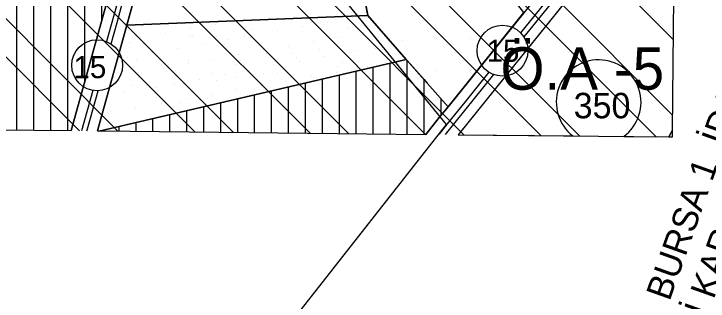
# Model space of a CAD drawing. Extents: x 409341 to 428634, y 4447481 to 4463281.
# Drawn here: x 420906.8 to 421316.4, y 4457678.8 to 4457848 of the extents above; entities that cross this region are included whole.
import ezdxf

# ---------------------------------------------------------------- set-up
doc = ezdxf.new("R2010")
doc.units = 0
for name, color, linetype in [('ADA', 7, 'Continuous'), ('ADAKENARI', 7, 'Continuous'), ('Default', 7, 'Continuous'), ('KALDIRIM', 7, 'Continuous'), ('KD_DAIRE', 7, 'Continuous'), ('KD_YGEN', 7, 'Continuous'), ('OA5', 7, 'Continuous'), ('PL_AYA_PARK_DINLENME', 7, 'Continuous'), ('PL_EĞİTİM', 7, 'Continuous'), ('PL_KON_MEV_250', 7, 'Continuous'), ('PL_KON_ONE_350', 7, 'Continuous'), ('SM_DAIRE', 7, 'Continuous'), ('SM_TAKS', 7, 'Continuous'), ('SN_TR_SIVILASMA', 7, 'Continuous'), ('TR_EĞİTİM', 7, 'Continuous'), ('TR_ORTAGELISME', 7, 'Continuous'), ('TR_ORTAYOGUNKONUT', 7, 'Continuous'), ('TR_PARKALANI', 7, 'Continuous')]:
    doc.layers.add(name, color=color, linetype=linetype)

# ---------------------------------------------------------------- blocks, each defined once
blk = doc.blocks.new('POINT_DISPLAY')
at = {"layer": 'Default'}
blk.add_line((0, 0), (0, 0), dxfattribs=at)

msp = doc.modelspace()

# ---------------------------------------------------------------- linework, layer by layer
at = {"layer": 'ADA'}
for p, q in [((421104.42, 4457904.65), (421115.69, 4457847.13)), ((421115.69, 4457847.13), (420973.4, 4457841.41)), ((421115.69, 4457847.13), (421138.25, 4457821.19)), ((421115.69, 4457847.13), (421138.25, 4457821.19)), ((421115.69, 4457847.13), (421138.25, 4457821.19)), ((420957.84, 4457779.09), (421138.25, 4457821.19)), ((421138.25, 4457821.19), (421162.95, 4457793.32)), ((421138.25, 4457821.19), (421162.95, 4457793.32)), ((421138.25, 4457821.19), (421150.6, 4457807.25)), ((421150.6, 4457807.25), (421162.95, 4457793.32)), ((421293.17, 4457775.55), (421295.4, 4457779.52))]:
    msp.add_line(p, q, dxfattribs=at)
at = {"layer": 'ADAKENARI'}
for p, q in [((420986.52, 4457944.4), (420940.52, 4457779.27)), ((420973.4, 4457841.41), (421000.97, 4457940.37)), ((421262.59, 4457892.95), (421168.94, 4457776.86)), ((421231.61, 4457878.44), (421162.95, 4457793.32)), ((421231.61, 4457878.44), (421162.95, 4457793.32)), ((421231.61, 4457878.44), (421162.95, 4457793.32)), ((420956.05, 4457779.11), (420973.4, 4457841.41)), ((421162.95, 4457793.32), (421157.8, 4457786.95)), ((421157.8, 4457786.95), (421149.83, 4457777.06))]:
    msp.add_line(p, q, dxfattribs=at)
at = {"layer": 'Default'}
msp.add_lwpolyline([(421050.15, 4457417.04), (421007.83, 4457463.42), (420944.65, 4457570.66), (421072.18, 4457668.63), (421162.04, 4457782.83), (421104.64, 4457852.98), (421094.21, 4457913.27), (421166.67, 4457928.34), (421162.04, 4458023.99), (421167.25, 4458044.28), (421186.38, 4458040.8), (421198.56, 4458072.69), (421246.09, 4458061.67), (421231.6, 4458019.35), (421275.66, 4457988.05), (421219.43, 4457901.09), (421239.14, 4457880.8), (421273.92, 4457924.86), (421286.67, 4457976.46), (421297.69, 4458041.38), (421309.86, 4458162.54), (421241.45, 4458159.64), (421240.3, 4458303.41)], dxfattribs=at)
at = {"layer": 'KALDIRIM'}
for p, q in [((420992.3, 4457942.79), (420961.36, 4457831.73)), ((420967.62, 4457843.02), (420995.19, 4457941.98)), ((421273.79, 4457916.39), (421207.69, 4457834.45)), ((421236.28, 4457874.67), (421205.77, 4457836.85)), ((420964.09, 4457830.32), (420967.62, 4457843.02)), ((421187.06, 4457813.66), (421172.78, 4457795.95)), ((421189.81, 4457812.29), (421161.29, 4457776.94)), ((420953.36, 4457802.98), (420946.74, 4457779.21)), ((420950.14, 4457780.25), (420956.42, 4457802.78)), ((421172.78, 4457795.95), (421162.47, 4457783.18)), ((420949.84, 4457779.18), (420950.14, 4457780.25)), ((421162.47, 4457783.18), (421157.47, 4457776.98))]:
    msp.add_line(p, q, dxfattribs=at)
at = {"layer": 'KD_DAIRE'}
for centre in [(421195.08, 4457826.33), (420955.86, 4457817.77)]:
    msp.add_circle(centre, 15, dxfattribs=at)
at = {"layer": 'PL_AYA_PARK_DINLENME'}
for p, q in [((420956.05, 4457779.11), (420957.84, 4457779.09)), ((421295.4, 4457779.52), (421293.17, 4457775.55))]:
    msp.add_line(p, q, dxfattribs=at)
for points in [[(420957.84, 4457779.09), (421138.25, 4457821.19), (421115.69, 4457847.13), (420973.4, 4457841.41), (420956.05, 4457779.11)], [(421293.17, 4457775.55), (421295.36, 4457775.52), (421295.4, 4457779.52)]]:
    msp.add_lwpolyline(points, dxfattribs=at)
at = {"layer": 'PL_EĞİTİM'}
msp.add_lwpolyline([(421207.76, 4457848.88), (421161.3, 4457908.23), (421148.7, 4457917.92), (421125.85, 4457911.41), (421104.42, 4457904.65), (421115.69, 4457847.13), (421138.25, 4457821.19), (421138.82, 4457820.55), (421148.82, 4457809.27), (421150.6, 4457807.25), (421162.95, 4457793.32), (421207.76, 4457848.88)], dxfattribs=at)
at = {"layer": 'PL_KON_MEV_250'}
for p, q in [((420940.52, 4457779.27), (420986.52, 4457944.4)), ((420822.23, 4457780.52), (420940.52, 4457779.27)), ((420957.84, 4457779.09), (421149.83, 4457777.06))]:
    msp.add_line(p, q, dxfattribs=at)
for points in [[(421000.97, 4457940.37), (420973.4, 4457841.41), (421115.69, 4457847.13), (421104.42, 4457904.65), (421125.85, 4457911.41), (421110.62, 4457996.56), (421168.14, 4458007.84), (421173.36, 4458034.24), (421194.4, 4458031.48), (421195.6, 4458036.07), (421202.94, 4458066.69), (421237.29, 4458058.84), (421222.97, 4458017.27), (421265.39, 4457988.9), (421209.89, 4457896.73), (421214.41, 4457892.92), (421231.61, 4457878.44), (421266.78, 4457922.04)], [(421149.83, 4457777.06), (421157.8, 4457786.95), (421162.95, 4457793.32), (421138.25, 4457821.19), (420957.84, 4457779.09)]]:
    msp.add_lwpolyline(points, dxfattribs=at)
at = {"layer": 'PL_KON_ONE_350'}
for p, q in [((421295.4, 4457779.52), (421296.46, 4457880.64)), ((421168.94, 4457776.86), (421293.17, 4457775.55)), ((421293.17, 4457775.55), (421295.4, 4457779.52))]:
    msp.add_line(p, q, dxfattribs=at)
msp.add_lwpolyline([(421296.46, 4457880.64), (421268.58, 4457894.28), (421262.59, 4457892.95), (421168.94, 4457776.86)], dxfattribs=at)
at = {"layer": 'SM_DAIRE'}
msp.add_line((421236.58, 4457776.14), (421266.66, 4457775.83), dxfattribs=at)
msp.add_arc((421251.83, 4457795.95), 25, 306.3763, 232.4122, dxfattribs=at)
at = {"layer": 'SN_TR_SIVILASMA'}
for p, q in [((421295.96, 4457832.82), (420847.49, 4458281.29)), ((421295.5, 4457788.39), (420847.49, 4458236.39)), ((421285.81, 4457775.62), (420847.49, 4458213.94)), ((421240.43, 4457776.1), (420847.49, 4458169.04)), ((421217.74, 4457776.34), (420847.49, 4458146.59)), ((420945.45, 4457779.22), (420581.04, 4458143.63)), ((420968.14, 4457778.98), (420603.49, 4458143.63)), ((421013.52, 4457778.5), (420648.4, 4458143.63)), ((421036.21, 4457778.26), (420670.85, 4458143.63)), ((421149.66, 4457777.06), (420783.1, 4458143.63)), ((421172.36, 4457776.82), (420805.55, 4458143.63)), ((421104.28, 4457777.54), (420872.43, 4458009.39)), ((421081.59, 4457777.78), (420863.44, 4457995.94))]:
    msp.add_line(p, q, dxfattribs=at)
at = {"layer": 'TR_ORTAGELISME'}
for p, q in [((421295.4, 4457779.52), (421296.46, 4457880.64)), ((421168.94, 4457776.86), (421236.58, 4457776.14)), ((421266.66, 4457775.83), (421293.17, 4457775.55)), ((421293.17, 4457775.55), (421295.4, 4457779.52))]:
    msp.add_line(p, q, dxfattribs=at)
msp.add_lwpolyline([(421296.46, 4457880.64), (421268.58, 4457894.28), (421262.59, 4457892.95), (421168.94, 4457776.86)], dxfattribs=at)
msp.add_arc((421251.83, 4457795.95), 25, 306.3763, 232.4122, dxfattribs=at)
at = {"layer": 'TR_ORTAYOGUNKONUT'}
for p, q in [((420908.59, 4457779.61), (420908.59, 4458334.88)), ((420918.59, 4457779.51), (420918.59, 4458334.8)), ((420928.59, 4457779.4), (420928.59, 4458333.66)), ((420938.59, 4457779.29), (420938.59, 4458331.65)), ((420948.59, 4457808.23), (420948.59, 4458065.76)), ((420958.59, 4457844.13), (420958.59, 4458040.79)), ((421138.82, 4457777.18), (421138.82, 4457820.55)), ((421118.82, 4457777.39), (421118.82, 4457816.65)), ((421128.82, 4457777.28), (421128.82, 4457818.98)), ((421108.82, 4457777.49), (421108.82, 4457814.32)), ((421088.82, 4457777.71), (421088.82, 4457809.65)), ((421098.82, 4457777.6), (421098.82, 4457811.98)), ((421148.82, 4457777.07), (421148.82, 4457809.27)), ((421068.82, 4457777.92), (421068.82, 4457804.98)), ((421078.82, 4457777.81), (421078.82, 4457807.32)), ((421048.82, 4457778.13), (421048.82, 4457800.32)), ((421058.82, 4457778.02), (421058.82, 4457802.65)), ((421038.82, 4457778.23), (421038.82, 4457797.98)), ((421158.82, 4457788.2), (421158.82, 4457797.98)), ((421018.82, 4457778.45), (421018.82, 4457793.32)), ((421028.82, 4457778.34), (421028.82, 4457795.65)), ((420998.82, 4457778.66), (420998.82, 4457788.65)), ((421008.82, 4457778.55), (421008.82, 4457790.98)), ((420978.82, 4457778.87), (420978.82, 4457783.98)), ((420988.82, 4457778.76), (420988.82, 4457786.32)), ((420968.82, 4457778.97), (420968.82, 4457781.65)), ((420958.82, 4457779.08), (420958.82, 4457779.32))]:
    msp.add_line(p, q, dxfattribs=at)
for points in [[(421000.97, 4457940.37), (420973.4, 4457841.41), (421115.69, 4457847.13), (421104.42, 4457904.65), (421125.85, 4457911.41), (421110.62, 4457996.56), (421168.14, 4458007.84), (421173.36, 4458034.24), (421194.4, 4458031.48), (421195.6, 4458036.07), (421202.94, 4458066.69), (421237.29, 4458058.84), (421222.97, 4458017.27), (421265.39, 4457988.9), (421209.89, 4457896.73), (421214.41, 4457892.92), (421231.61, 4457878.44), (421266.78, 4457922.04)], [(420940.52, 4457779.27), (420986.52, 4457944.4)]]:
    msp.add_lwpolyline(points, dxfattribs=at)

# ---------------------------------------------------------------- block references
at = {"layer": 'TR_EĞİTİM', "xscale": 0.1, "yscale": 0.10000000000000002}
for p in [(421156.18, 4457833.43), (421176.39, 4457833.74), (421194.74, 4457833.43), (421136.3, 4457832.45), (421156.18, 4457814.72), (421175.94, 4457814.94)]:
    msp.add_blockref('POINT_DISPLAY', p, dxfattribs=at)
at = {"layer": 'TR_PARKALANI', "xscale": 0.1, "yscale": 0.10000000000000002}
for p in [(421106.54, 4457845.82), (421106.54, 4457845.82), (421026.02, 4457841.77), (421026.02, 4457841.77), (421082.52, 4457842.92), (421082.52, 4457842.92), (421089.52, 4457841.89), (421091.77, 4457843.21), (421091.77, 4457843.21), (421119.93, 4457841.61), (421119.93, 4457841.61), (420982.64, 4457840.43), (420986.5, 4457840.67), (421011.25, 4457839.17), (421011.25, 4457839.17), (421046.69, 4457838.96), (421046.69, 4457838.96), (421062.23, 4457838), (421062.23, 4457838), (421077, 4457840.61), (421077, 4457840.61), (421104.29, 4457839.29), (420981.71, 4457833.96), (420981.71, 4457833.96), (420996.48, 4457836.57), (420996.48, 4457836.57), (421010.85, 4457835), (421010.85, 4457835), (421012.18, 4457835.22), (421042.59, 4457834.93), (421047.45, 4457835.4), (421047.45, 4457835.4), (421098.43, 4457834.23), (421098.43, 4457834.23), (421113.2, 4457836.84), (421113.2, 4457836.84), (420975.01, 4457831.03), (420975.01, 4457831.03), (421017.91, 4457830.19), (421017.91, 4457830.19), (421026.95, 4457832.62), (421032.68, 4457832.79), (421032.68, 4457832.79), (421068.89, 4457829.02), (421068.89, 4457829.02), (421083.66, 4457831.63), (421083.66, 4457831.63), (420988.37, 4457824.98), (420988.37, 4457824.98), (421003.14, 4457827.59), (421003.14, 4457827.59), (421054.12, 4457826.42), (421054.12, 4457826.42), (421056.5, 4457827.41), (421071.27, 4457824.8), (421086.91, 4457827.12), (421105.09, 4457825.25), (421105.09, 4457825.25), (421109.47, 4457826.37), (421119.86, 4457827.86), (421119.86, 4457827.86), (420973.59, 4457822.38), (420973.59, 4457822.38), (420979.17, 4457820.73), (421024.57, 4457821.21), (421024.57, 4457821.21), (421039.34, 4457823.81), (421039.34, 4457823.81), (421073.63, 4457822.4), (421090.32, 4457822.65), (421090.32, 4457822.65), (421133.81, 4457820.69), (421133.81, 4457820.69), (420993.94, 4457818.13), (421009.58, 4457820.45), (421009.8, 4457818.61), (421009.8, 4457818.61), (421037.79, 4457818.44), (421060.78, 4457817.44), (421060.78, 4457817.44), (421075.55, 4457820.04), (421075.55, 4457820.04), (421097.98, 4457816.73), (421097.98, 4457816.73), (421100.81, 4457819.59), (421115.59, 4457816.99), (421126.52, 4457818.88), (421126.52, 4457818.88), (420980.25, 4457813.4), (420980.25, 4457813.4), (420995.03, 4457816), (420995.03, 4457816), (421001.96, 4457814.48), (421023.48, 4457812.92), (421046, 4457814.83), (421046, 4457814.83), (421053.89, 4457812.63), (421062.14, 4457812.76), (421062.14, 4457812.76), (421096.98, 4457813.67), (421096.98, 4457813.67), (421111.75, 4457816.27), (421111.75, 4457816.27), (420965.48, 4457810.79), (420965.48, 4457810.79), (420966.12, 4457810.52), (421016.46, 4457809.63), (421016.46, 4457809.63), (421026.3, 4457808.8), (421026.3, 4457808.8), (421031.23, 4457812.23), (421031.23, 4457812.23), (421038.25, 4457810.31), (421067.44, 4457808.46), (421067.44, 4457808.46), (421082.21, 4457811.06), (421082.21, 4457811.06), (420976.56, 4457805.96), (420986.92, 4457804.42), (420986.92, 4457804.42), (420990.47, 4457804.84), (420990.47, 4457804.84), (421001.69, 4457807.02), (421001.69, 4457807.02), (421052.66, 4457805.86), (421052.66, 4457805.86), (421067.8, 4457805.11), (420972.14, 4457801.81), (420972.14, 4457801.81), (421023.12, 4457800.65), (421023.12, 4457800.65), (421037.89, 4457803.25), (421037.89, 4457803.25), (420990.46, 4457798.43), (421008.35, 4457798.04), (421008.35, 4457798.04), (421020.88, 4457798.15), (420978.8, 4457792.83), (420978.8, 4457792.83), (420993.58, 4457795.44), (420993.58, 4457795.44), (421005.24, 4457795.83), (420964.03, 4457790.23), (420964.03, 4457790.23), (420957.45, 4457783.95)]:
    msp.add_blockref('POINT_DISPLAY', p, dxfattribs=at)

# ---------------------------------------------------------------- texts
at = {"layer": 'Default'}
for s, p in [('18.10.2018 TARİHLİ KARARI İLE YÜRÜTMESİ DURDURULMUŞTUR. (BBMK: 28.12.2018/2840)', (421256.46, 4457501.97)), ("BURSA 1. İDARE MAHKEMESİ'NİN 2017/849 E. SAYI VE ", (421293.63, 4457678.34))]:
    msp.add_text(s, height=15, rotation=70.3879, dxfattribs=at).set_placement(p)
at = {"layer": 'KD_YGEN'}
for p in [(421185.72, 4457819.79), (420941.94, 4457810.15)]:
    msp.add_text('15', height=13, dxfattribs=at).set_placement(p)
at = {"layer": 'OA5'}
msp.add_text('Ö.A -5', height=25, dxfattribs=at).set_placement((421193.89, 4457803.33))
at = {"layer": 'SM_TAKS'}
msp.add_text('350', height=15, dxfattribs=at).set_placement((421237.09, 4457786.51))

doc.saveas('drawing.dxf')
